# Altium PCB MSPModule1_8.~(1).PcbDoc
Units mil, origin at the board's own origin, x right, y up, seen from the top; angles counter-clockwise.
Board outline 2000 x 1440 mil, 2 copper layers (Top Layer, Bottom Layer); 52 components, 59 nets, 273 pads, 97 vias.
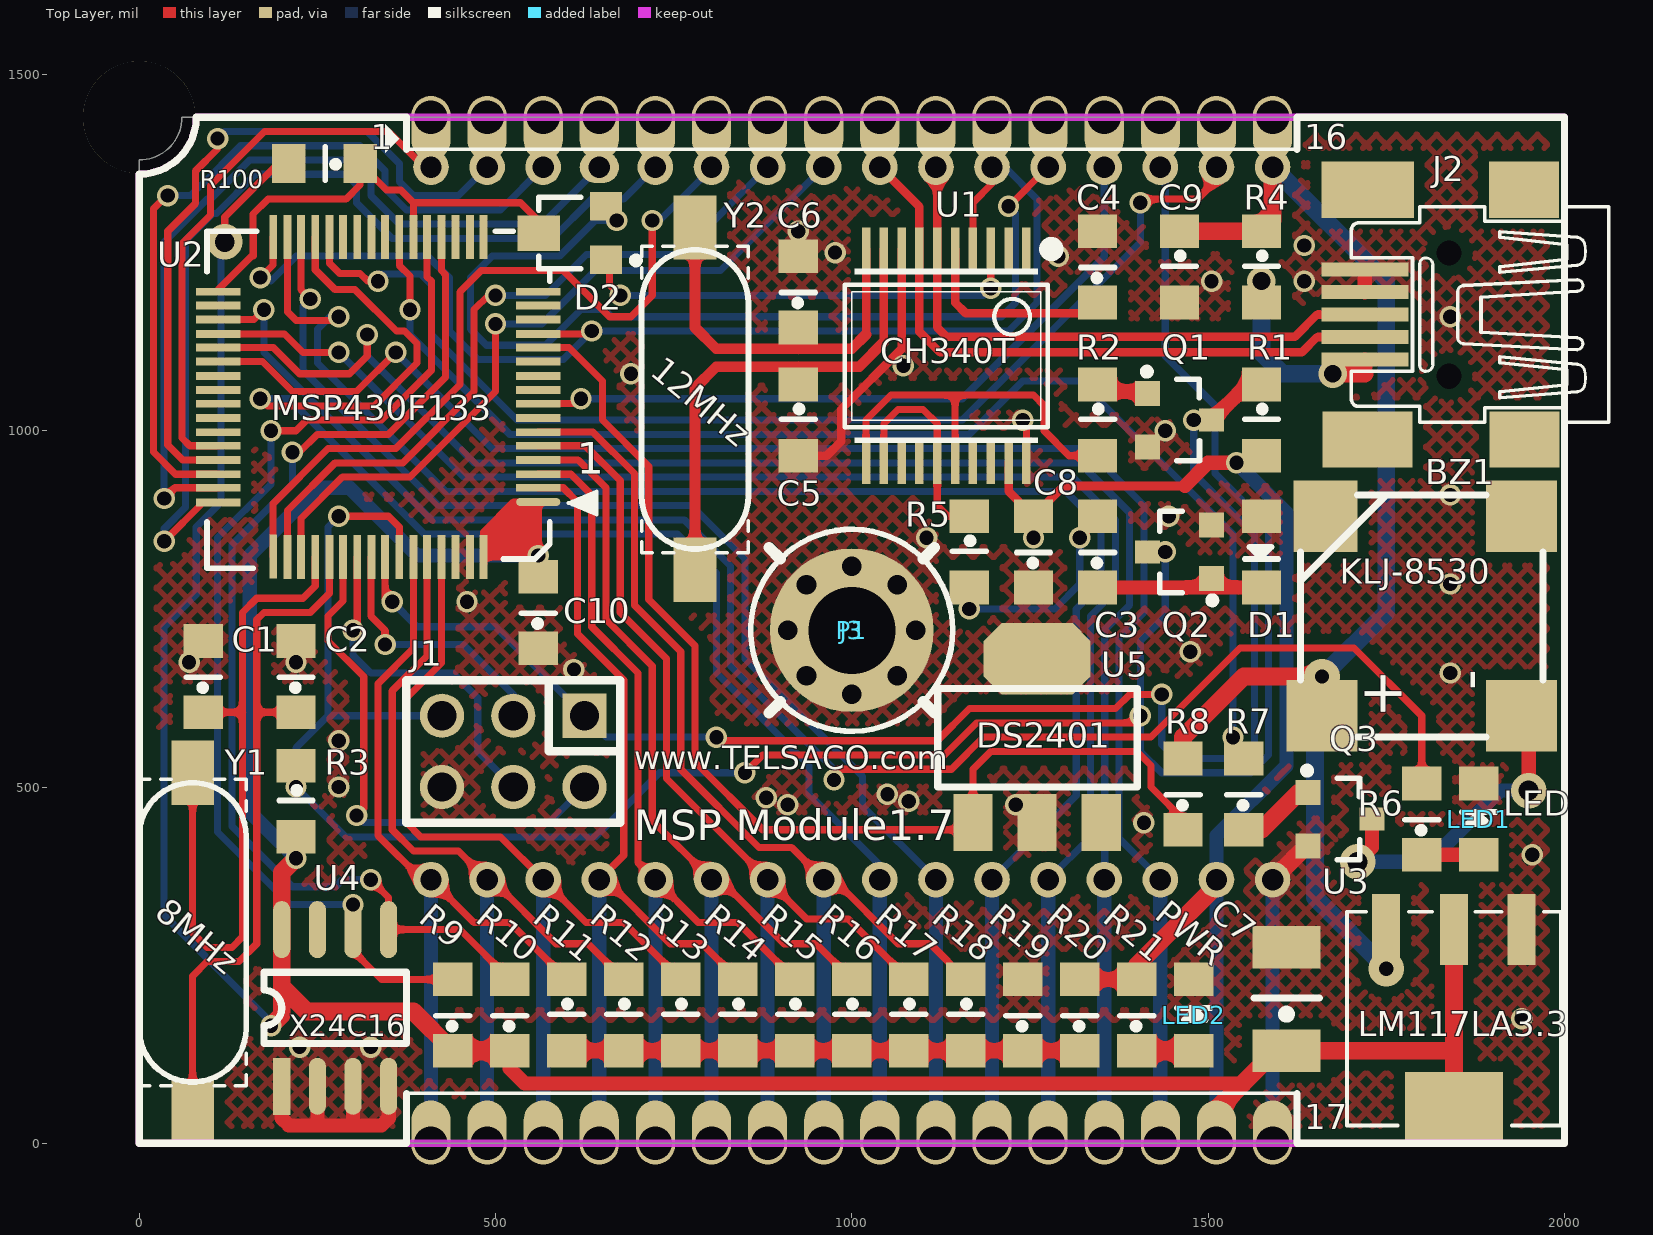
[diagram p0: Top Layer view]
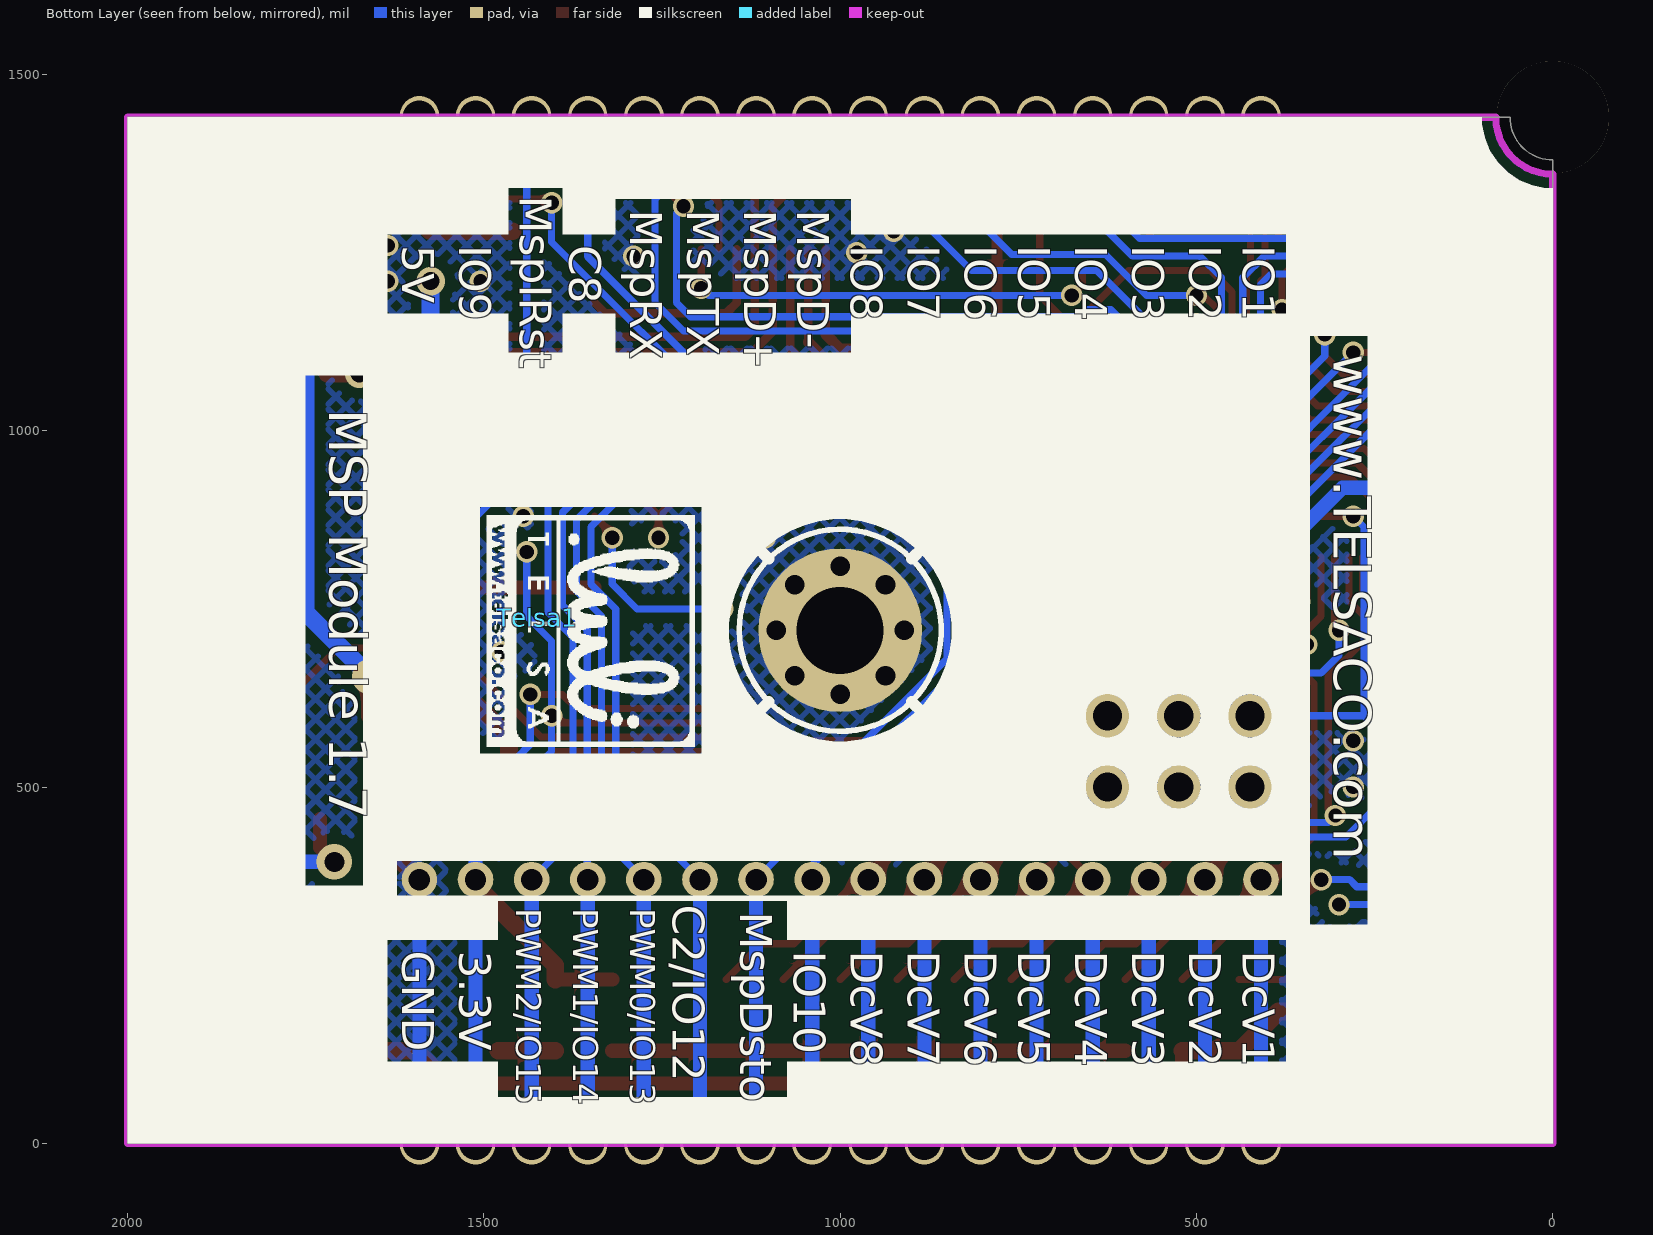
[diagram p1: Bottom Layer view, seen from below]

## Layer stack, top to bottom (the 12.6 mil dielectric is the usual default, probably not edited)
Top Solder: solder mask 0.4, Solder Resist, Dk 3.5
Top Layer: signal copper 1.4
Dielectric1: dielectric 12.6, FR-4, Dk 4.8
Bottom Layer: signal copper 1.4
Bottom Solder: solder mask 0.4, Solder Resist, Dk 3.5

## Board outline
0,0 2000,0 2000,1440 60,1440 cw(c0,1440) 0,1380

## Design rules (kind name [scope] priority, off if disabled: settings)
Clearance Clearance_2 [(InComponent('U1') AND InComponent('U2') AND InComponent('U3') AND InComponent('U4'))] p1: gap=7.5 ignorepadtopadclearanceinfootprint=FALSE except(0: Arc-Hole Track-Hole SMDPad-Hole THPad-Hole Via-Hole Fill-Hole Poly-Hole Region-Hole Text-Hole)
Clearance Clearance_1 [InPoly] p2: gap=15 ignorepadtopadclearanceinfootprint=FALSE except(0: Arc-Hole Track-Hole SMDPad-Hole THPad-Hole Via-Hole Fill-Hole Poly-Hole Region-Hole Text-Hole)
Clearance [All] p3: gap=10 ignorepadtopadclearanceinfootprint=FALSE except(0: Arc-Hole Track-Hole SMDPad-Hole THPad-Hole Via-Hole Fill-Hole Poly-Hole Region-Hole Text-Hole)
ComponentClearance [All] p1: gap=0 collisioncheckmode=3 verticalgap=10 showdistances=FALSE
DiffPairsRouting [All] p1: maxlimit=100 minlimit=10 mostfreqgap=10 toplayer_minwidth=10 toplayer_maxwidth=15 toplayer_prefwidth=15 bottomlayer_minwidth=10 bottomlayer_maxwidth=15 bottomlayer_prefwidth=15 maxuncoupledlength=500
HoleSize [All] p1: absolutevalues=TRUE maxlimit=200 minlimit=1 maxpercent=80.000 minpercent=20.000
HoleToHoleClearance [All] p1: gap=0 allowstackedmicrovias=TRUE
MinimumSolderMaskSliver [All] p1: minsoldermaskwidth=0
NetAntennae [All] p1: netantennaetolerance=1
PlaneConnect [All] p1: planeconnectstyle=Direct reliefexpansion=20 reliefentries=4 reliefconductorwidth=10 reliefairgap=10
PolygonConnect [All] p1: connectstyle=Direct reliefconductorwidth=10 reliefentries=4 polygonreliefangle="90 Angle" airgapwidth=10
RoutingVias [All] p1: holewidth=28 width=50 viastyle="Through Hole" minholewidth=10 minwidth=10 maxholewidth=28 maxwidth=50
SilkToSilkClearance [All] p1: silktosilkclearance=0
SilkToSolderMaskClearance SilkscreenOverComponentPads [IsPad] p1: minsilkscreentomaskgap=0 clearancetoexposedcopper=TRUE
SolderMaskExpansion [All] p1: expansion=4
Width [All] p1: maxlimit=100 minlimit=1 preferedwidth=20 minimp=50.000000 maximp=50.000000 favimp=50.000000
21 further rules are at their usual default settings.

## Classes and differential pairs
differential pair OSC2: +OSC2_P -OSC2_N
differential pair OSC1: +OSC1_P -OSC1_N
differential pair D: +D_P -D_N

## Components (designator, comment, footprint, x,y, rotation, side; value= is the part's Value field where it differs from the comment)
BZ1 "KLJ-8530" "BUZZER SMD" 1800,740 r270 top
C1 "33pf" 0805T 90,605 r90 top
C2 "33pf" 0805T 220,605 r90 top
C3 "1uF" 0805T 1345,780 r90 top
C4 "10nF" 0805T 1345,1180 r90 top
C5 "22pf" 0805T 925,1065 r270 top
C6 "22pf" 0805T 925,1145 r90 top
C7 "100uF" 1210T 1610,130 r90 top
C8 "100nF" 0805T 1255,780 r90 top
C9 "10nF" 0805T 1460,1280 r270 top
C10 "100nF" 0805T 560,695 r90 top
D1 "1N4148" 0805-D#1 1575,880 r270 top
D2 "BAT54A" SOT23 655,1240 r90 top
J1 "CON6A" IDC6 625,600 r180 top
J2 "IN/D+&D-" "MINI USB" 1720,1100 r270 top
J3 "MspModule" MSPMODULE_2MM 1000,0 r0 top
LED1 "LED" 0805-D#2 1880,405 r90 top
LED2 "PWR" 0805-D#2 1480,130 r90 top
P1 "3.1mm" SCREW3.1 1000,720 r0 top
Q1 "2n2222" SOT23_3 1460,1015 r0 top
Q2 "2n2222" SOT23_3 1460,830 r180 top
Q3 "2n2222" SOT23_3 1685,455 r0 top
R1 "4K7" 0805R 1575,1065 r270 top
R2 "1k" 0805R 1345,1065 r270 top
R3 "4K7" 0805R 220,530 r270 top
R4 "1R" 0805R 1575,1280 r270 top
R5 "100K" 0805R 1165,880 r270 top
R6 "270R" 0805R 1800,405 r90 top
R7 "1K" 0805R 1550,440 r90 top
R8 "1k" 0805R 1465,440 r90 top
R9 "1k" 0805R 440,130 r90 top
R10 "1k" 0805R 520,130 r90 top
R11 "270K" 0805R 600,230 r270 top
R12 "270K" 0805R 680,230 r270 top
R13 "270K" 0805R 760,230 r270 top
R14 "270K" 0805R 840,230 r270 top
R15 "270K" 0805R 920,230 r270 top
R16 "270K" 0805R 1000,230 r270 top
R17 "270K" 0805R 1080,230 r270 top
R18 "270K" 0805R 1160,230 r270 top
R19 "0R" 0805R 1240,130 r90 top
R20 "0R" 0805R 1320,130 r90 top
R21 "270R" 0805R 1400,130 r90 top
R100 "4.7K" 0805R 310,1375 r180 top
Telsa1 "ARM Telsa" ARM1 1425,737.5 r0 bottom
U1 "CH340T" SSOP20 1245,1255 r180 top
U2 "MSP430F133" MSP64 560,900 r270 top
U3 "LM117LA3.3" LM117 1845,175 r90 top
U4 "X24C16" SO-8 200,80 r90 top
U5 "DS2401" DS2401 1260,690 r0 top
Y1 "8MHz" CRYSTAL-SMD#1 75,45 r90 top
Y2 "12MHz" CRYSTAL-SMD#2 780,1295 r270 top

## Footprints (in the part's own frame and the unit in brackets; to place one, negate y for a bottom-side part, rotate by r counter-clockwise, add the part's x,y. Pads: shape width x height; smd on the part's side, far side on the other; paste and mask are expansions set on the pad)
0805-D#1 [mm]
  rect 1.2x1.4 smd: A(0,0) K(2.54,0)
  silkscreen extent 1.09,-0.6 1.52,0.6, body extent 0.42,-0.43 2.07,0.37, height 0.65
0805-D#2 [mm]
  rect 1.2x1.4 smd: 1(0,0) 2(2.54,0)
  silkscreen extent 1.09,-0.6 1.52,0.6, body extent 0.25,-0.62 2.27,0.63, height 1.1
0805R [mm]
  rect 1.2x1.4 smd: 1(0,0) 2(2.54,0)
  silkscreen extent 0.78,-0.6 1.25,0.6, body extent 0.3,-0.62 2.3,0.63, height 0.78
0805T [mm]
  rect 1.2x1.4 smd: 1(0,0) 2(2.54,0)
  silkscreen extent 0.78,-0.6 1.25,0.6, body extent 0.14,-0.74 2.34,0.71, height 0.86
1210T [mil]
  rect 60x95 smd: 1(0,0) 2(145,0)
  silkscreen extent 45,-46 74,45, body extent 10,-49 136,49, height 24
ARM1 [mil]
  silkscreen extent -221,-143 71,181
"BUZZER SMD" [mil]
  rect 100x100 smd: +(140,-140) -(140,140) NC(-140,140)
  rect 100x90 smd: NC(-140,-135)
  silkscreen extent -170,-170 170,170, body extent -170,-167 165,167, height 159
CRYSTAL-SMD#1 [mil]
  rect 90x60 smd: 1(0,0) 2(475,0)
  Top Layer pour cut-out: 116,-75 87.3,-69.29 62.97,-53.03 46.71,-28.7 41,0 41,0 46.71,28.7 62.97,53.03 87.3,69.29 116,75 116,75 386,75 414.7,69.29 439.03,53.03 455.29,28.7 461,0 461,0 455.29,-28.7 439.03,-53.03 414.7,-69.29 386,-75 386,-75
  silkscreen extent 36,-75 466,75, body extent -1,-93 499,93, height 165
CRYSTAL-SMD#2 [mil]
  rect 90x60 smd: 1(10,0) 2(490,0)
  Top Layer pour cut-out: 116,-75 87.3,-69.29 62.97,-53.03 46.71,-28.7 41,0 41,0 46.71,28.7 62.97,53.03 87.3,69.29 116,75 116,75 386,75 414.7,69.29 439.03,53.03 455.29,28.7 461,0 461,0 455.29,-28.7 439.03,-53.03 414.7,-69.29 386,-75 386,-75
  silkscreen extent 36,-75 466,75, body extent -1,-93 499,93, height 165
DS2401 [mil]
  oct 150x100 smd: 1(0,-10)
  rect 55x80 smd: 2(-90,-240) 3(90,-240) 4(0,-240)
  silkscreen extent -139,-190 141,-52, body extent -128,-263 128,11, height 65
IDC6 [mil]
  rect 62x62 hole 41: 1(0,0)
  round 62 hole 41: 2(0,100) 3(100,0) 4(100,100) 5(200,0) 6(200,100)
  silkscreen extent -50,-50 250,150, body extent -50,-50 250,150, height 313
LM117 [mm]
  rect 2.54x1 smd: 1(3.175,-2.413) 2(3.175,0) 3(3.175,2.413)
  rect 2.54x3.5 smd: 2(-3.175,0)
  silkscreen extent -3.81,-3.81 3.81,3.81, body extent -3.56,-3.25 3.4,3.25, height 1.66
"MINI USB" [mm]
  rect 0.5x3.1 smd: 1(0,0) 2(-0.8,0) 3(-1.6,0) 4(-2.4,0) 5(-3.2,0)
  rect 2x2.5 smd: M1(-6.05,5.67) M2(2.85,5.695)
  rect 2x3.2 smd: M3(2.85,0.1)
  rect 2x3.3 smd: M4(-6.05,0.1)
  round 0.635 hole 0.9: ""(-3.8,3) ""(0.6,3)
  silkscreen extent -5.44,-0.48 2.24,8.7, body extent -6.47,-0.18 3.43,9.02, height 4.14
MSP64 [mil]
  oval 11x62 smd: 1(0,0)
  rect 11x62 smd: 2(-20,0) 3(-39,0) 4(-59,0) 5(-79,0) 6(-98,0) 7(-118,0) 8(-138,0) 9(-157,0) 10(-177,0) 11(-197,0) 12(-217,0) 13(-236,0) 14(-256,0) 15(-276,0) 16(-295,0) 33(-295,-449) 34(-276,-449) 35(-256,-449) 36(-236,-449) 37(-217,-449) 38(-197,-449) 39(-177,-449) 40(-157,-449) 41(-138,-449) 42(-118,-449) 43(-98,-449) 44(-79,-449) 45(-59,-449) 46(-39,-449) 47(-20,-449) 48(0.5,-449)
  rect 62x11 smd: 17(-372,-77) 18(-372,-96) 19(-372,-116) 20(-372,-136) 21(-372,-156) 22(-372,-175) 23(-372,-195) 24(-372,-215) 25(-372,-234) 26(-372,-254) 27(-372,-274) 28(-372,-293) 29(-372,-313) 30(-372,-333) 31(-372,-352) 32(-372,-372) 49(76.5,-372) 50(77,-352) 51(77,-333) 52(77,-313) 53(77,-293) 54(77,-274) 55(77,-254) 56(77,-234) 57(77,-215) 58(77,-195) 59(77,-175) 60(77,-156) 61(77,-136) 62(77,-116) 63(77,-96) 64(77,-77)
  silkscreen extent -380,-465 93,82, body extent -375,-452 81,4, height 39
MSPMODULE_2MM [mil]
  round 50 hole 30 mask+0: 1(-590.55,1370) 2(-511.81,1370) 3(-433.07,1370) 5(-275.59,1370) 6(-196.85,1370) 7(-118.11,1370) 8(-39.37,1370) 9(39.37,1370) 10(118.11,1370) 11(196.85,1370) 12(275.59,1370) 13(354.33,1370) 14(433.07,1370) 15(511.81,1370) 16(590.55,1370) 17(590.55,370) 18(511.81,370) 19(433.07,370) 20(354.33,370) 21(275.59,370) 22(196.85,370) 23(118.11,370) 24(39.37,370) 25(-39.37,370) 26(-118.11,370) 27(-196.85,370) 28(-275.59,370) 29(-354.33,370) 30(-433.07,370) 31(-511.81,370) 32(-590.55,370)
  oval 55x90 hole 47 copper offset 0,-15 mask+0: 1(-590.55,1440) 2(-511.81,1440) 3(-433.07,1440) 4(-354.33,1440) 5(-275.59,1440) 6(-196.85,1440) 7(-118.11,1440) 8(-39.37,1440) 9(39.37,1440) 10(118.11,1440) 11(196.85,1440) 12(275.59,1440) 13(354.33,1440) 14(433.07,1440) 15(511.81,1440) 16(590.55,1440)
  oval 55x45 hole 30 mask+0: 4(-354.33,1370)
  oval 55x90 hole 47 copper offset 0,15 mask+0: 17(590.55,0) 18(511.81,0) 19(433.07,0) 20(354.33,0) 21(275.59,0) 22(196.85,0) 23(118.11,0) 24(39.37,0) 25(-39.37,0) 26(-118.11,0) 27(-196.85,0) 28(-275.59,0) 29(-354.33,0) 30(-433.07,0) 31(-511.81,0) 32(-590.55,0)
  silkscreen extent -1000,0 1000,1440
SCREW3.1 [mil]
  round 230 hole 122.05: 0(0,0)
  silkscreen extent -142,-142 142,142
SO-8 [mil]
  rect 80x24 smd: 1(0,0)
  oval 80x24 smd: 2(0,-50) 3(0,-100) 4(0,-150) 5(220,-150) 6(220,-100) 7(220,-50) 8(220,0)
  silkscreen extent 60,-175 160,25, body extent -8,-171 228,21, height 63
SOT23 [mil]
  rect 40x45 smd: 1(0,0) 2(74.8,0)
  rect 50x60 smd: 3(37.4,94.49)
  silkscreen extent -13,-47 88,94, body extent -21,-5 97,93, height 41
SOT23_3 [mil] "SOT23, 3-Leads, Body 2.9x2.5mm (max), Pitch 0.95mm, IPC Medium Density"
  rect 35x35 smd: 1(-45,37.5) 2(-45,-37.5)
  rect 35x32 smd: 3(45,0)
  silkscreen extent -51,-57 28,73, body extent -49,-56 45,58, height 40
SSOP20 [mil]
  rect 12x60 smd: 1(0,0) 2(25,0) 3(50,0) 4(75,0) 5(100,0) 6(125,0) 7(150,0) 8(175,0) 9(200,0) 10(225,0) 11(225,300) 12(200,300) 13(175,300) 14(150,300) 15(125,300) 16(100,300) 17(75,300) 18(50,300) 19(25,300) 20(0,300)
  silkscreen extent -42,-7 255,273, body extent -32,-9 257,302, height 77

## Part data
BZ1: library part BUZZER_0, "Buzzer"
C1 C2 C4 C5 C6: library part "CAP NP_Dup2", "Capacitor"
C3: library part "CAP NP_1", "Capacitor"
C7 C9: library part CAP_1, "Capacitor"
C8 C10: library part "CAP NP_Dup1", "Capacitor"
D1: library part Diode, "Diode"
J1: library part CON4A_0, "Header 2*3 Male"
J2: library part 4N49_8, "USB Connector"
J3: library part CON14_16
LED1: library part LED_2
LED2: library part LED_2, "LED"
P1: library part Screw
Q1 Q2 Q3: library part NPN_4, "NPN Transistor"
R1 R2 R3 R4 R5 R6 R7 R8 R9 R10 R11 R12 R13 R14 R15 R16 R17 R18 R19 R20 R21: library part R_0_Dup2, "Resistor"
R100: library part RES_SMD_0805
Telsa1: library part "ARM Tellsa"
U1: library part CON20A_2, "USB to Serial chip"
U2: library part CON89_1, "16-bit Microcontroller"
U3: library part LM117LA_0, "Regulator"
U4: library part X24C16_1, "Serial E2PROM"
U5: library part CON4A_3, "Silicon Serial Number"
Y1 Y2: library part CRYSTAL, "Crystal Oscillator"

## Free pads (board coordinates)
  round 157.48 hole 157.48: 2(0,1440)

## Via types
v1: diameter 30, hole 20, Top Layer to Bottom Layer, tented bottom, 78 vias
v2: diameter 39.37, hole 27.56, Top Layer to Bottom Layer, 8 vias
v3: diameter 30, hole 20, Top Layer to Bottom Layer, 4 vias
v4: diameter 50, hole 28, Top Layer to Bottom Layer, 3 vias
v5: diameter 40, hole 25, Top Layer to Bottom Layer, 2 vias
v6: diameter 50, hole 20, Top Layer to Bottom Layer, 2 vias

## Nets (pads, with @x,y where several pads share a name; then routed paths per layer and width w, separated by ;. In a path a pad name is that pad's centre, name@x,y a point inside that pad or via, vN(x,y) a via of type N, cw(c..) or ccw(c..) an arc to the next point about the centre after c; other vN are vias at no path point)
3.3: C7.1 C8.2 C10.2 J3.18 R1.2 R3.2 R9.1 R10.1 R20.2 R21.2 R100.2 U1.19 U2.1 U2.64 U3.2 U4.8 | length 6635.3
  Top Layer w10: v4(120,1265) 120,1300 195,1375 R100.2 ; v1(220,400) R3.2 ; v1(1255,850) C8.2 ; U2.64 560,823 v1(560,825) U2.1 525,900 483,858 U2.64
  Top Layer w12: U1.19 1220,915 C8.2 1297.5,922.5 1467.5,922.5
  Top Layer w20: R10.1 520,105 541.12,83.88 1548.88,83.88 ; R20.2 R21.2 ; 1467.5,922.5 1500,955 v1(1540,955)
  Top Layer w25: v3(185,165) 200,180 200,220 ; v1(220,400) 200,380 U4.8 200,220 ; R10.1 R9.1 385,185 235,185 200,220 ; R21.2 1400,250 1511.81,361.81 J3.18@1511.81,370 ; J3.18@1511.81,27.5 1511.81,46.81 1548.88,83.88 1595,130 C7.1 1845,130 ; U3.2@1845,50 1845,130 ; U3.2@1845,300 1845,130
  Bottom Layer w10: v4(120,1265) 115,1260 115,900 80,865 80,770 35,725 35,320 185,170 v3(185,165)
  Bottom Layer w20: v1(220,400) 155,465 155,825 250,920 295,920 390,825 v1(560,825) ; J3.18@1511.81,0 1511.81,370 1511.81,431.81 1610,530 1610,885 v1(1540,955)
5: BZ1.+ C9.1 J3.16 R4.1 R8.2 U3.3 | length 1855.5
  Top Layer w25: C9.1 R4.1 1590.55,1295.55 J3.16@1590.55,1370 ; R8.2 1465,570 1550,655 v6(1660,655) BZ1.+ ; v6(1750,245) U3.3
  Bottom Layer w25: J3.16@1590.55,1370 1750,1210.55 1750,745 v6(1660,655) 1650,645 1650,345 v6(1750,245)
5USB: J2.1 R4.2 | length 277.4
  Top Layer w20: 1720,1080 J2.1
  Top Layer w25: v5(1675,1080) 1720,1080
  Bottom Layer w25: v5(1575,1210) 1575,1110 1605,1080 v5(1675,1080)
ALARMLED: R6.2 U2.35 | length 2311
  Top Layer w10: U2.35 161,1156 v1(175,1170) ; v1(975,510) 975,520 980,525 1140,525 1185,570 1420,570 1545,695 1705,695 1800,600 R6.2
  Bottom Layer w10: v1(175,1170) 175,1110 410,875 765,875 830,810 830,670 975,525 v1(975,510)
BUZ: R7.2 U2.23 | length 1807.5
  Top Layer w10: U2.23 365,1232.03 380,1217.03 v1(380,1170) ; v1(1535,570) 1535,555 R7.2
  Bottom Layer w10: v1@380,1180 v1(380,1170) 380,1135 520,995 1165,995 1240,1070 1320,1070 1535,855 v1(1535,570)
C2: J3.22 U2.31 | length 2392.5
  Top Layer w10: U2.31 208,1167 220,1155 275,1155 v1(280,1160)
  Bottom Layer w10: v1(280,1160) 267.57,1160 250,1142.43 250,1095 430,915 1300,915 1350,865 1350,785 1315,750 1315,488.15 J3.22@1196.85,370
  Bottom Layer w20: J3.22@1196.85,0 J3.22@1196.85,370
C8: J3.13 U2.8 | length 1005.5
  Top Layer w10: U2.8 613,1038 v1(620,1045)
  Bottom Layer w10: v1(620,1045) 1155,1045 1354.33,1244.33 J3.13@1354.33,1370
D_N: J2.2 J3.9 U1.7 | length 900
  Top Layer w12: J3.9@1039.37,1370 1095,1314.37 U1.7 1095,1138.89 1123.89,1110 1631.48,1110 1652.98,1131.5 J2.2
D_P: J2.3 J3.10 U1.6 | length 844
  Top Layer w12: J3.10@1118.11,1370 1120,1368.11 U1.6 1120,1145 1133,1132 1621.98,1132 1652.98,1162.99 J2.3
DCV1: J3.32 R11.1 U2.59 | length 1130.7
  Top Layer w10: U2.59 385,695 335,645 335,431.72 396.72,370 409.45,370 409.38,370.07 409.52,370.07 469.59,310 520,310 R11.1
  Bottom Layer w20: J3.32@409.45,0 J3.32@409.45,370
DCV2: J3.31 R12.1 U2.60 | length 1185.3
  Top Layer w10: U2.60 404,684 355,635 355,440 385,410 448.19,410 488.19,370 495,370 585,280 630,280 R12.1
  Bottom Layer w20: J3.31@488.19,0 J3.31@488.19,370
DCV3: J3.30 R13.1 U2.61 | length 1239.4
  Top Layer w10: U2.61 424,674 375,625 375,450 395,430 506.93,430 566.93,370 626.93,310 680,310 R13.1
  Bottom Layer w20: J3.30@566.93,0 J3.30@566.93,370
DCV4: J3.29 R14.1 U2.2 | length 1256.7
  Top Layer w10: U2.2 595,920 615,900 615,715 680,650 680,404.33 645.67,370 655,370 745,280 790,280 R14.1
  Bottom Layer w20: J3.29@645.67,0 J3.29@645.67,370
DCV5: J3.28 R15.1 U2.3 | length 1293.9
  Top Layer w10: U2.3 606,939 635,910 635,725 700,660 700,394.41 J3.28@724.41,370 ; J3.28@720,374.41 J3.28@724.41,370 ; R15.1 840,310 784.41,310 J3.28@724.41,370
  Bottom Layer w20: J3.28@724.41,0 J3.28@724.41,370
DCV6: J3.27 R16.1 U2.4 | length 1347.4
  Top Layer w10: U2.4 616,959 655,920 655,735 720,670 720,453.15 803.15,370 815,370 905,280 950,280 R16.1
  Bottom Layer w20: J3.27@803.15,0 J3.27@803.15,370
DCV7: J3.26 R17.1 U2.5 | length 1407.1
  Top Layer w10: U2.5 626,979 675,930 675,745 740,680 740,511.89 881.89,370 936.89,315 995,315 R17.1
  Bottom Layer w20: J3.26@881.89,0 J3.26@881.89,370
DCV8: J3.25 R18.1 U2.6 | length 1493.1
  Top Layer w10: U2.6 637,998 695,940 695,755 760,690 760,525 870,415 915.63,415 960.63,370 975,370 1065,280 1110,280 R18.1
  Bottom Layer w20: J3.25@960.63,0 J3.25@960.63,370
GND: C1.2 C2.2 C4.2 C5.2 C6.2 C7.2 C8.1 C9.2 C10.1 D1.A J1.6 J2.4 J2.5 J3.17 LED1.2 LED2.2 P1.0 Q1.2 Q2.2 Q3.2 R19.2 U1.8 U1.20 U2.62 U2.63 U3.1 U4.1 U4.2 U4.3 U4.4 U5.1 U5.4 | length 1330.7
  Top Layer w10: v1(70,675) 70,685 C1.2 ; v1(220,675) C2.2 ; U1.20 v1@1245,1015
  Top Layer w12: C5.2 965,965 985,985 985,1030 1070,1115 U1.8
  Top Layer w20: U4.1 200,35 210,25 300,25 ; 250,25 U4.2 ; U4.3 300,25 ; U4.4 350,35 340,25 300,25 ; J2.4 J2.5
  Top Layer w25: J3.17@1590.55,370 1638.05,417.5 Q3.2
  Bottom Layer w20: J3.17@1590.55,0 J3.17@1590.55,370
  other v1: 225,135 325,135 1940,175 1955,405 1410,450 910,475 1230,475 1080,480 880,485 1050,490 280,500 1840,660 610,665 1475,690 460,760 1840,785 1105,850 1445,880 1840,910 1440,1000 1240,1015 690,1080 1072.5,1091.35 1840,1160 1505,1210 1635,1210 1290,1245 976.59,1250 1635,1260 925,1280
  other v2: 1000,630 936.36,656.36 1063.64,656.36 910,720 1090,720 936.36,783.64 1063.64,783.64 1000,810
  other v3: 280,565
ICTS: R2.2 U1.11 U1.16 | length 550.2
  Top Layer w10: U1.11 1020,1015 1055,1050 1145,1050 ; U1.16 1145,1050 ; R2.2 1305,965 1270,1000 1270,1035 1255,1050 1145,1050
IDSR: R5.1 U1.12 U1.15 | length 312.8
  Top Layer w10: U1.12 1045,1010 1065,1030 1100,1030 1120,1010 U1.15 1120,895 1135,880 R5.1
IO1: J3.1 U2.44 | length 787.8
  Top Layer w10: U2.44 71,979 60,990 60,1262.61 100,1302.61 100,1344 176,1420 350,1420 400,1370 J3.1@409.45,1370
IO2: J3.2 U2.45 | length 989.5
  Top Layer w10: v1(110,1410) 110,1395.5 78.69,1364.19 78.69,1318.69 40,1280 40,980 61,959 U2.45
  Bottom Layer w10: v1(110,1410) 120,1420 320,1420 365,1375 365,1350 385,1330 448.19,1330 J3.2@488.19,1370
IO3: J3.3 U2.46 | length 1104.1
  Top Layer w10: v1@38.33,1330 20,1311.67 20,970 51,939 U2.46
  Bottom Layer w10: v1(40,1330) 71.86,1330 86.86,1345 87.43,1345 142.43,1400 310,1400 345,1365 345,1340 375,1310 506.93,1310 J3.3@566.93,1370
IO4: J3.4 U2.47 | length 1185.5
  Top Layer w10: v1(35,905) 50,920 U2.47
  Bottom Layer w10: v1(35,905) 35,1264.85 95.15,1325 100,1325 155,1380 300,1380 325,1355 325,1330 365,1290 565.67,1290 J3.4@645.67,1370
IO5: J3.5 U2.48 | length 1324
  Top Layer w10: v1(35,845) 89.5,899.5 U2.48
  Bottom Layer w10: v1(35,845) 35,862.57 65,892.57 65,1266.57 103.43,1305 108.28,1305 163.28,1360 290,1360 305,1345 305,1320 355,1270 580,1270 635,1325 679.41,1325 J3.5@724.41,1370
IO6: J3.6 U2.49 | length 1078
  Top Layer w10: U2.49@187.5,823.5 187.5,897.5 265,975 360,975 450,1065 450,1195 480,1225 595,1225 660,1160 690,1160 720,1190 v1(720,1295)
  Bottom Layer w10: v1(720,1295) 730,1295 803.15,1368.15 J3.6@803.15,1370
IO7: J3.7 U2.50 | length 1005.9
  Top Layer w10: U2.50 208,888 275,955 370,955 470,1055 470,1170 490,1190 v1(500,1190)
  Bottom Layer w10: v1(500,1190) 570,1190 627.5,1247.5 759.39,1247.5 J3.7@881.89,1370
IO8: J3.8 U2.51 | length 1047.5
  Top Layer w10: U2.51 227,877 285,935 380,935 500,1055 v1(500,1150)
  Bottom Layer w10: v1(500,1150) 565,1150 640,1225 815.63,1225 J3.8@960.63,1370
IO9: J3.15 U2.28 | length 1608
  Top Layer w10: U2.28 267,1235.03 281.37,1220.67 310,1220.67 320.67,1210 v3(335,1210) ; v1(1405,1320) 1410,1325 1485,1325 1511.81,1351.81 J3.15@1511.81,1370
  Bottom Layer w10: v3@335,1220 395,1220 410,1205 410,1135 530,1015 1155,1015 1405,1265 v1(1405,1320)
IO10: J3.24 U2.29 | length 2144.8
  Top Layer w10: v1(170,1045) 180,1035 330,1035 390,1095 390,1122.43 372.43,1140 361,1140 303,1198 275,1198 247,1226 U2.29
  Bottom Layer w10: v1(170,1045) 210,1045 400,855 755,855 810,800 810,660 940,530 940,490 1039.37,390.63 J3.24@1039.37,370
  Bottom Layer w20: J3.24@1039.37,0 J3.24@1039.37,370
IO11: J3.23 U2.30 | length 1857.3
  Top Layer w10: U2.30 227,1198 v1(240,1185)
  Bottom Layer w10: v1(240,1185) 230,1175 230,1085 420,895 775,895 850,820 850,680 1015,515 1015,473.11 J3.23@1118.11,370
  Bottom Layer w20: J3.23@1118.11,0 J3.23@1118.11,370
IO13: J3.21 U2.36 | length 2288.3
  Top Layer w10: U2.36 204,1136 230,1110 v1(280,1110)
  Bottom Layer w10: v1@270,1110 v1@275,1105 ; v1(280,1110) 455,935 1310,935 1370,875 1370,775 1335,740 1335,429.41 J3.21@1275.59,370
  Bottom Layer w20: J3.21@1275.59,0 J3.21@1275.59,370
IO14: J3.20 U2.37 | length 2355.6
  Top Layer w10: U2.37 188,1117 225,1080 295,1080 320,1105 v1(320,1135)
  Bottom Layer w10: v1(320,1135) 320,1105 470,955 1320,955 1390,885 1390,755.67 1355,720.67 1355,370.67 J3.20@1354.33,370
  Bottom Layer w20: J3.20@1354.33,0 J3.20@1354.33,370
IO15: J3.19 U2.38 | length 2361.8
  Top Layer w10: U2.38 173,1097 215,1055 305,1055 v1(360,1110)
  Bottom Layer w10: v1(360,1110) 495,975 1330,975 1410,895 1410,745 1375,710 1375,428.07 J3.19@1433.07,370
  Bottom Layer w20: J3.19@1433.07,0 J3.19@1433.07,370
IPCRX: J3.11 U1.4 U2.13 U2.32 | length 1720.4
  Top Layer w10: v3(170,1215) 187.5,1232.5 U2.32@187.5,1272 ; U2.13 631,1136 v1(635,1140) ; U1.4 1170,1320 1196.85,1346.85 J3.11@1196.85,1370
  Bottom Layer w10: 185,1210 220,1245 405,1245 435,1215 435,1140 475,1100 595,1100 v1(635,1140) 1220,1140 1260,1180 1260,1325 1215,1370 J3.11@1196.85,1370
IPCTX: D2.1 U1.3 | length 625.4
  Top Layer w10: D2.1@660,1230 660,1205 v1(675,1190) ; v1(1195,1200) U1.3
  Bottom Layer w10: v1(675,1190) 1185,1190 v1(1195,1200)
MSPIRST: J1.5 J3.14 Q2.3 R3.1 U2.58 | length 3375.7
  Top Layer w10: v1(220,500) R3.1 ; v1(280,880) 350,880 365,865 U2.58@365,845 ; v1(850,520) 875,545 1130,545 1175,590 1395,590 v1(1405,600)
  Bottom Layer w10: v1(280,880) 265,865 265,600 ; J1.5 265,600 ; v1(850,520) 730,520 640,430 290,430 v1(220,500) 220,555 265,600 ; J3.14@1433.07,1370 1440,1363.07 1440,1105 1510,1035 1510,940 1585,865 1585,545 1560,520 1435,520 1405,550 v1(1405,600) 1405,705 1440,740 v1(1440,830)
MSPRX: D2.3 R100.1 U2.22 U2.33 | length 682.4
  Top Layer w10: U2.33@111,1196.5 111,1198.43 157.57,1245 159.5,1245 160,1245.5 160,1281.57 159.75,1281.82 159.75,1304.12 180.63,1325 290,1325 310,1345 R100.1 347.12,1337.88 367.12,1337.88 385,1320 ; U2.22 385,1320 ; D2.3@565.51,1272.4 565.51,1289.49 535,1320 385,1320
MSPRX_: D2.2 J3.12 | length 1342.8
  Top Layer w10: v1(670,1295) 670.2,1295 675,1290.2 v1@674.8,1290 ; v1(1220,1315) 1220.59,1315 J3.12@1275.59,1370
  Bottom Layer w10: v1(670,1295) 640,1295 590,1245 495,1245 465,1215 465,1142.57 487.57,1120 570,1120 620,1170 652.57,1170 662.57,1160 1210,1160 1230,1180 1230,1305 v1(1220,1315)
MSPTCK: J1.1 Q1.3 R1.1 U2.57 | length 2045.3
  Top Layer w10: U2.57 345,770 v1(355,760) ; v1(810,570) 815,565 1120,565 1165,610 1370,610 1390,630 v1(1435,630)
  Top Layer w20: Q1.3 1555,1065 R1.1
  Bottom Layer w10: v1(355,760) 390,725 500,725 J1.1 655,570 v1(810,570) ; v1(1435,630) 1435,560 1455,540 1550,540 1565,555 1565,855 1480,940 v1@1480,1005
  other v1: 1480,1015
MSPTDI: J1.4 U2.55 | length 486
  Top Layer w10: v1(300,720) 306,726 U2.55
  Bottom Layer w10: v1(300,720) 300,685 325,660 440,660 475,625 475,550 J1.4
MSPTDO: J1.2 U2.54 | length 741.4
  Top Layer w10: U2.54 286,761 265,740 265,705 315,655 315,470 v1(305,460)
  Bottom Layer w10: v1(305,460) 315,450 575,450 J1.2
MSPTMS: J1.3 U2.56 | length 370.3
  Top Layer w10: U2.56@325,823 325,740 345,720 v1(345,700)
  Bottom Layer w10: v1(345,700) 455,700 525,630 J1.3
NetBZ1_-: BZ1.- Q3.3 | length 458.8
  Top Layer w20: v4(1710,395) 1730,415 Q3.3 ; BZ1.- 1950,590 v4(1950,495)
  Bottom Layer w20: v4(1710,395) 1810,395 1910,495 v4(1950,495)
NetC3_1: C3.1 D1.K Q2.1 | length 230
  Top Layer w20: C3.1 D1.K
NetC3_2: C3.2 R5.2 | length 304.9
  Top Layer w10: v1(1165,750) R5.2 ; v1(1320,850) 1320,855 C3.2
  Bottom Layer w10: v1(1165,750) 1285,750 1320,785 v1(1320,850)
NetC4_1: C4.1 U1.5 | length 287.4
  Top Layer w12: U1.5 1145,1180 1160,1165 1330,1165 C4.1
NetLED1_1: LED1.1 R6.1 | length 79
  Top Layer w20: R6.1 LED1.1@1879,405
NetLED2_1: LED2.1 R21.1 | length 80
  Top Layer w25: R21.1 LED2.1
NetQ1_1: Q1.1 R2.1 | length 57.5
  Top Layer w20: R2.1@1345,1055 Q1.1@1402.5,1055
NetQ3_1: Q3.1 R7.1 | length 111.7
  Top Layer w25: R7.1 1575,440 1627.5,492.5 Q3.1
NetR8_1: R8.1 U2.12 U5.2 | length 1584.1
  Top Layer w10: U2.12 603,1117 650,1070 650,1015 715,950 715,763.28 780,698.28 780,535 875,440 1160,440 U5.2 1170,525 1195,550 1400,550 1420,530 1420,500 1465,455 R8.1
NetR11_2: R11.2 R12.2 R13.2 R14.2 R15.2 R16.2 R17.2 R18.2 R19.1 R20.1 | length 720
  Top Layer w20: R11.2 R12.2 R13.2 R14.2 R15.2 R16.2 R17.2 R18.2 R19.1 R20.1
OSC1_N: C2.1 U2.53 Y1.1 | length 967
  Top Layer w10: Y1.1 75,235 95,255 140,255 165,280 165,605 ; C2.1@210,605 165,605 ; U2.53 267,772 240,745 175,745 165,735 165,605
OSC1_P: C1.1 U2.52 Y1.2 | length 967.8
  Top Layer w10: Y1.2 75,295 95,275 130,275 145,290 145,605 ; C1.1@100,605 145,605 ; U2.52 247,782 230,765 165,765 145,745 145,605
OSC2_N: C5.1 U1.9 Y2.2 | length 702.1
  Top Layer w12: 1045,1124.64 U1.9
  Top Layer w15: Y2.2 780,1060 810,1090 1010.36,1090 1045,1124.64 ; C5.1 925,1090
OSC2_P: C6.1 U1.10 Y2.1 | length 550.7
  Top Layer w12: 1020,1135 U1.10
  Top Layer w15: Y2.1 780,1145 810,1115 1000,1115 1020,1135 ; 925,1115 C6.1
SCL: R9.2 U2.21 U4.6 | length 1462.7
  Top Layer w10: v1(185,1000) 220,1000 235,1015 340,1015 410,1085 410,1210 404,1216 U2.21 ; U4.6 300,270 340,230 R9.2
  Bottom Layer w10: v1(185,1000) 185,925 110,850 110,436.72 211.72,335 v1(300,335)
SDA: R10.2 U2.20 U4.5 | length 1531.9
  Top Layer w10: v1(215,970) 225,970 250,995 350,995 430,1075 430,1219 424,1225 U2.20 ; v1(325,370) 350,345 U4.5 450,300 R10.2
  Bottom Layer w10: v1(215,970) 215,925 130,840 130,445 215,360 275,360 285,370 v1(325,370)
pads on no net: BZ1.NC J2. J2.M1 J2.M2 J2.M3 J2.M4 U1.1 U1.2 U1.13 U1.14 U1.17 U1.18 U2.7 U2.9 U2.10 U2.11 U2.14 U2.15 U2.16 U2.17 U2.18 U2.19 U2.24 U2.25 U2.26 U2.27 U2.34 U2.39 U2.40 U2.41 U2.42 U2.43 U4.7 U5.3

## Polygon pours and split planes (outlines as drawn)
no net on Bottom Overlay "Top Layer-No Net" (solid): 0,0 2000,0 2000,1440 100,1440 cw(c0,1440) 0,1340
GND on Top Layer "Top Layer-GND" (hatched 45Degree grid 20 track 8, remove dead copper, pour order 2): 2000,0 2000,1440 190,1440 0,1250 0,0
GND on Bottom Layer "Bottom Layer-GND" (hatched 45Degree grid 20 track 8, remove dead copper, pour order 4): 2000,0 2000,1320 5,1320 0,1325 0,0

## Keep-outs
Keep-Out Layer:
  lines w10: 0,0 0,1360 ccw(c0,1440) 80,1440 2000,1440 2000,0 0,0

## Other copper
Top Layer:
  pour cut-out: 1520,415 1580,415 1580,565 1520,565
  region net 3.3: 483,860 523,900 558.5,900 560,823 483,823

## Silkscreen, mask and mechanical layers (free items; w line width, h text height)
Top Overlay:
  text "www.TELSACO.com" at 695,525 h33
  text "MSP Module1.7" at 695,425 h43
Bottom Overlay:
  pour cut-out: 1110,610 ccw(c1000,720) 1110,830 ccw(c1000,720) 890,830 ccw(c1000,720) 890,610 ccw(c1000,720)
  pour cut-out: 425,630 ccw(c425,600) 395,600 ccw(c425,600) 425,570 ccw(c425,600) 455,600 ccw(c425,600)
  pour cut-out: 525,630 ccw(c525,600) 495,600 ccw(c525,600) 525,570 ccw(c525,600) 555,600 ccw(c525,600)
  pour cut-out: 625,630 ccw(c625,600) 595,600 ccw(c625,600) 625,570 ccw(c625,600) 655,600 ccw(c625,600)
  pour cut-out: 455,500 ccw(c425,500) 425,530 ccw(c425,500) 395,500 ccw(c425,500) 425,470 ccw(c425,500)
  pour cut-out: 555,500 ccw(c525,500) 525,530 ccw(c525,500) 495,500 ccw(c525,500) 525,470 ccw(c525,500)
  pour cut-out: 655,500 ccw(c625,500) 625,530 ccw(c625,500) 595,500 ccw(c625,500) 625,470 ccw(c625,500)
  pour cut-out: 1750,1077.5 1750,362.5 1670,362.5 1670,1077.5
  pour cut-out: 380,396 1622,396 1622,348 380,348
  pour cut-out: 380,1258 1622,1258 1622,1210 380,1210
  pour cut-out: 375,285 1635,285 1635,115 375,115
  pour cut-out: 1075,65 1075,340 1480,340 1480,65
  pour cut-out: 985,1110 985,1325 1315,1325 1315,1110
  pour cut-out: 375,1275 1635,1275 1635,1165 375,1165
  pour cut-out: 1390,1110 1390,1340 1465,1340 1465,1110
  pour cut-out: 1195,892.5 1505,892.5 1505,547.5 1195,547.5
  pour cut-out: 340,1132.5 340,307.5 260,307.5 260,1132.5
  text "www.TELSACO.com" at 325,1107.5 h90 r90
  text "MSP Module 1.7" at 1735,1030 h90 r90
